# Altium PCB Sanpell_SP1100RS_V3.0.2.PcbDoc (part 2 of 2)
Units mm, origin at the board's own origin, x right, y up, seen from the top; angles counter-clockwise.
Board outline 126.12 x 87.13 mm, 4 copper layers (TopLayer, GND, PWR, BottomLayer); 152 components, 95 nets, 511 pads, 171 vias.
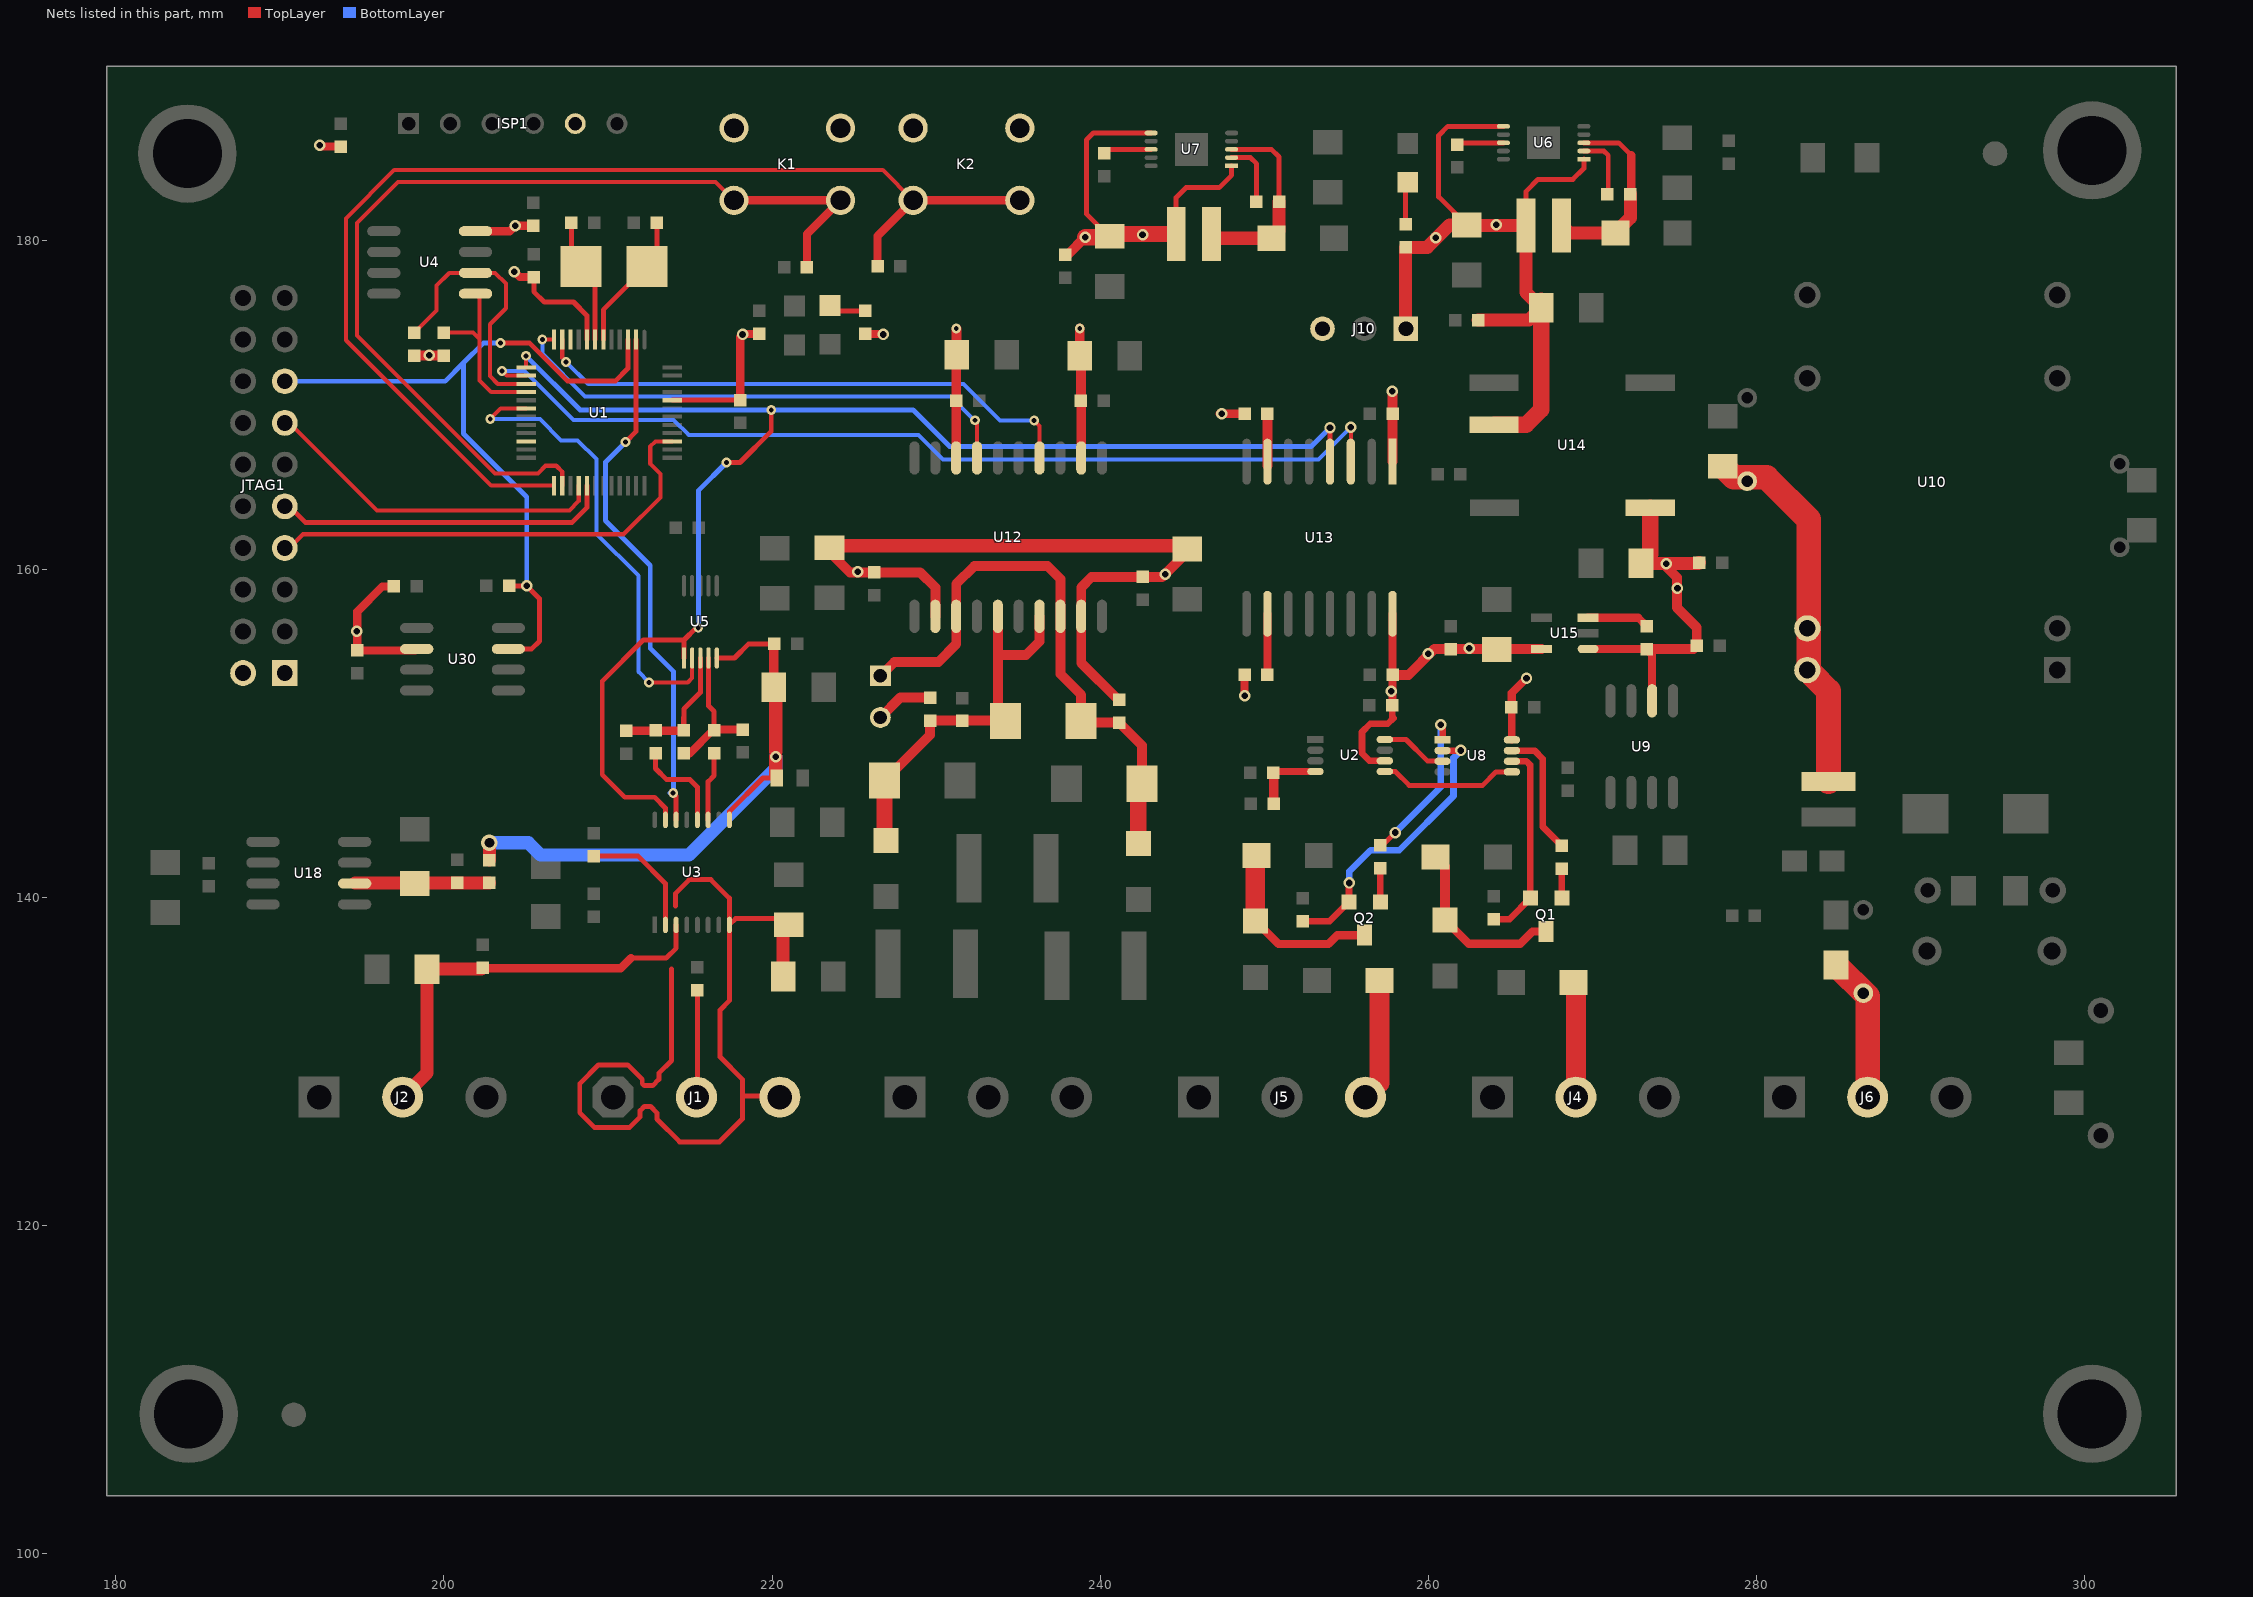
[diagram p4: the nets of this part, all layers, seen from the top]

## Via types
v1: diameter 0.7, hole 0.4, TopLayer to BottomLayer, 122 vias
v2: diameter 0.6, hole 0.3, TopLayer to BottomLayer, 40 vias
v3: diameter 1, hole 0.6, TopLayer to BottomLayer, 9 vias

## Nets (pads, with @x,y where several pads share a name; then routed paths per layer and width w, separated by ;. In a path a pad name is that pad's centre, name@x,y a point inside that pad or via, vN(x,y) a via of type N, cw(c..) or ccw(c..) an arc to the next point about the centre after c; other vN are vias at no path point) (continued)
NetD7_A: LD3.A R52.1 | length 2.2
  TopLayer w0.3: LD3.A@223.523,175.734 R52.1@225.682,175.734
NetD8_A: LD1.A R18.1 | length 2.4
  TopLayer w0.3: R18.1@258.607,181.005 LD1.A@258.607,183.448
NetFB1_1: C26.1 CA1.1 FB1.1 U18.6 | length 8.2
  TopLayer w0.8: U18.6@194.596,140.875 FB1.1@202.775,140.875
NetFB2_1: C6.1 FB2.1 U2.4 | length 4.5
  TopLayer w0.4: C6.1@250.548,147.587 250.63,147.669 U2.4@253.111,147.669
  TopLayer w0.6: C6.1@250.548,147.587 250.575,147.56 FB2.1@250.575,145.7
NetJ1_2: J1.2 R16.2 | length 6.6
  TopLayer w0.3: J1.2@215.392,127.823 215.45,127.881 R16.2@215.45,134.353
NetJ4_2: D4.2 J4.2 | length 7
  TopLayer w1.2: D4.2@268.842,134.803 268.986,134.659 J4.2@268.986,127.823
NetJ5_3: D5.2 J5.3 | length 7.5
  TopLayer w1.2: J5.3@256.159,127.823 257.017,128.681 D5.2@257.017,134.928
NetJ6_3: C04.1 F3.1 J6.2 | length 8.8
  TopLayer w1.5: F3.1@284.85,135.875 286.766,133.959 J6.2@286.766,127.823
NetL3_2: C02.1 L3.2 U10.22 U10.23 | length 23
  TopLayer w1.5: C02.1@277.925,166.277 278.6,165.602 280.598,165.602 283.175,163.025 283.175,156.39 283.175,153.935 283.188,153.913 283.41,153.55 284.375,152.585 L3.2@284.375,147.06
NetQ1_3: D1.2 F1.1 Q1.3 | length 11.1
  TopLayer w0.5: F1.1@261,138.625 262.45,137.175 265.6,137.175 266.345,137.92 Q1.3@267.165,137.92
  TopLayer w0.6: D1.2@260.44,142.447 261,141.888 F1.1@261,138.625
NetQ2_3: D2.2 F2.1 Q2.3 | length 11.5
  TopLayer w0.5: F2.1@249.45,138.554 250.854,137.15 253.9,137.15 254.445,137.695 Q2.3@256.098,137.695
  TopLayer w1.2: F2.1@249.45,138.554 249.45,142.482 D2.2@249.515,142.547
NetR3_1: C14.2 C34.1 R3.1 U5.3 | length 9.2
  TopLayer w0.3: C34.1@214.597,150.147 214.597,150.972 214.625,151 ; C34.1@214.625,150.175 214.625,151 ; U5.3@215.63,154.587 215.63,152.48 214.625,151.475 214.625,151
  TopLayer w0.5: C14.2@211.1,150.147 C34.1@214.597,150.147
NetR7_2: Q1.1 R7.2 | length 1.8
  TopLayer w0.4: Q1.1@268.13,139.952 R7.2@268.13,141.738
NetR12_1: C34.2 C35.1 R12.1 U5.4 | length 8.7
  TopLayer w0.3: U5.4@216.13,154.587 216.13,151.67 216.462,151.338 R12.1@216.462,150.181 ; R12.1@216.506,150.225 R12.1@216.575,150.294
  TopLayer w0.5: C34.2@214.625,148.778 214.984,148.778 R12.1@216.387,150.181 ; R12.1@216.506,150.225 C35.1@218.2,150.225
NetR13_2: Q2.1 R13.2 | length 2
  TopLayer w0.4: Q2.1@257.063,139.727 R13.2@257.063,141.765
NetR70_2: R70.2 U13.7 | length 3.2
  TopLayer w0.6: U13.7@250.19,166.296 R70.2@250.19,169.471
NetT1_2: R76.2 T1.2 | length 3.5
  TopLayer w0.6: T1.2@226.6,150.96 227.812,152.172 R76.2@229.625,152.172
NetU1_7: C16.1 U1.7 Y1.2 | length 7.1
  TopLayer w0.3: Y1.2@207.772,178.816 C16.1@207.772,181.102 ; Y1.2@208.344,178.435 209.217,177.562 U1.7@209.217,173.99
NetU2_5: U2.5 U8.5 | length 8.4
  TopLayer w0.3: U2.5@257.341,147.669 257.982,147.669 258.826,146.825 263.3,146.825 264.119,147.644 U8.5@265.088,147.644
NetU2_8: U2.8 U8.3 | length 4.1
  TopLayer w0.3: U2.8@257.341,149.619 258.631,149.619 259.931,148.319 U8.3@260.858,148.319
NetU3_2: R6.1 U3.2 | length 7.6
  TopLayer w0.3: R6.1@209.137,142.512 211.836,142.512 213.502,140.846 U3.2@213.502,138.321
NetU3_11: R12.2 U3.11 | length 4.3
  TopLayer w0.3: U3.11@216.102,144.721 216.102,147.052 216.462,147.412 R12.2@216.462,148.784 R12.2@216.55,148.696
NetU3_12: R3.2 U3.12 | length 5.9
  TopLayer w0.3: R3.2@212.9,148.778 212.9,147.85 213.575,147.175 215,147.175 215.452,146.723 U3.12@215.452,144.721
NetU6_2: C22.1 U6.2 | length 4
  TopLayer w0.3: U6.2@269.468,185.481 270.693,185.481 270.955,185.219 C22.1@270.955,182.85
NetU6_3: C22.2 D49.2 L1.1 U6.3 | length 11.8
  TopLayer w0.3: U6.3@269.468,185.981 271.59,185.981 272.352,185.219
  TopLayer w0.5: C22.2@272.352,182.85 272.352,185.219
  TopLayer w0.8: L1.1@268.11,180.95 268.573,180.487 D49.2@271.386,180.487 272.307,181.408 C22.2@272.307,182.85
NetU6_8: R8.1 U6.8 | length 2.9
  TopLayer w0.3: R8.1@261.76,185.875 261.866,185.981 U6.8@264.568,185.981
NetU7_2: C10.1 U7.2 | length 4
  TopLayer w0.3: U7.2@248.002,185.079 249.153,185.079 249.526,184.706 C10.1@249.526,182.4
NetU7_3: C10.2 D9.2 L2.1 U7.3 | length 11.6
  TopLayer w0.3: U7.3@248.002,185.579 250.431,185.579 250.897,185.113 C10.2@250.897,182.4
  TopLayer w0.8: L2.1@247.041,180.164 D9.2@250.44,180.164 250.897,180.621 C10.2@250.897,182.4
NetU7_8: R11.1 U7.8 | length 2.9
  TopLayer w0.3: R11.1@240.25,185.35 240.479,185.579 U7.8@243.102,185.579
NetU8_1: R13.1 U8.1 | length 9.9
  TopLayer w0.3: R13.1@257.063,143.162 257.187,143.162 v1(257.975,143.95)
  TopLayer w0.4: v1(260.75,150.525) 260.858,150.417 U8.1@260.858,149.594
  BottomLayer w0.4: v1(257.975,143.95) 260.75,146.725 v1(260.75,150.525)
NetU8_2: Q2.2 R4.1 U8.2 | length 17.5
  TopLayer w0.4: R4.1@252.325,138.55 253.981,138.55 Q2.2@255.158,139.727 255.158,140.858 v1(255.175,140.875) ; U8.2@260.858,148.944 261.969,148.944 v1(261.975,148.95)
  BottomLayer w0.4: v1(255.175,140.875) 255.175,141.575 256.475,142.875 258.225,142.875 261.525,146.175 261.525,148.5 v1(261.975,148.95)
NetU8_6: Q1.2 R5.1 U8.6 | length 12.1
  TopLayer w0.4: R5.1@263.975,138.675 264.948,138.675 Q1.2@266.225,139.952 266.192,139.985 266.192,148.07 265.968,148.294 U8.6@265.088,148.294
NetU8_7: R7.1 U8.7 | length 7.9
  TopLayer w0.4: U8.7@265.088,148.944 266.461,148.944 266.954,148.451 266.954,144.311 R7.1@268.13,143.135
NetU12_13: F10.1 R41.2 T1.1 U12.13 U12.18 ZD14.1 ZD15.1 | length 36.2
  TopLayer w0.6: T1.1@226.6,153.5 227.45,154.35 230.15,154.35 231.22,155.42 U12.13@231.22,157.123 231.22,159.095 232.325,160.2 236.779,160.2 237.57,159.409 U12.18@237.57,157.123 237.57,153.605 238.825,152.35 ZD14.1@238.825,150.75 238.922,150.653 R41.2@241.15,150.653 242.55,149.253 ZD15.1@242.55,146.925 ; F10.1@242.316,142.94 F10.1@242.316,143.29
  TopLayer w1: F10.1@242.316,143.29 242.316,146.691 ZD15.1@242.55,146.925
NetU12_15: F11.1 R42.1 R76.1 U12.15 U12.17 ZD14.2 ZD16.2 | length 24.1
  TopLayer w0.6: ZD16.2@226.85,147.125 229.625,149.9 R76.1@229.625,150.775 ZD14.2@234.2,150.775 ; U12.15@233.76,157.123 233.76,154.95 ; ZD14.2@234.225,150.75 ZD14.2@234.2,150.775 ; U12.17@236.3,157.123 236.3,155.6 235.475,154.775 233.935,154.775 233.76,154.95 ; 233.76,154.95 233.76,151.215 ZD14.2@234.2,150.775
  TopLayer w1: ZD16.2@226.85,147.125 226.85,143.574 F11.1@226.949,143.475
NetU13_10: R71.1 U13.10 | length 3.7
  TopLayer w0.5: R71.1@250.19,153.556 U13.10@250.19,157.279
NetU15_3: R72.2 U15.3 | length 3.8
  TopLayer w0.5: U15.3@269.73,157.038 272.784,157.038 R72.2@273.3,156.522
NetY1_1: C15.1 U1.6 Y1.1 | length 9.3
  TopLayer w0.3: U1.6@209.717,173.99 209.717,175.808 212.344,178.435 Y1.1@212.369,178.435 Y1.1@211.328,177.394 ; Y1.1@212.979,178.816 C15.1@212.979,181.102
PT1000: C25.1 C30.1 J2.2 U3.3 | length 25.5
  TopLayer w0.3: 211.4,136.3 213.55,136.3 214.152,136.902 U3.3@214.152,138.321
  TopLayer w0.5: C30.1@202.35,135.675 210.775,135.675 211.4,136.3
  TopLayer w0.8: J2.2@197.485,127.823 198.975,129.313 C25.1@198.975,135.625 C30.1@202.3,135.625
R\E\S\E\T\: JTAG1.15 R68.2 U1.3 U30.7 | length 46.7
  TopLayer w0.3: v2(203.45,173.775) 205.225,173.775 207.525,171.475 210.464,171.475 211.217,172.228 U1.3@211.217,173.99 ; U30.7@203.934,155.14 205.357,155.14 205.825,155.608 205.825,158.2 v1(205.05,158.975) R68.2@203.972,158.975
  BottomLayer w0.3: JTAG1.15@190.581,171.45 200.075,171.45 201.2,172.575 ; v2(203.45,173.775) 202.4,173.775 201.2,172.575 ; v1(205.05,158.975) 205.05,164.4 201.2,168.25 201.2,172.575
REF2.5V: C8.1 C11.1 C17.1 FB1.2 U3.9 U5.5 | length 37.6
  TopLayer w0.3: U5.5@216.63,154.587 217.713,154.587 218.575,155.45 C11.1@220.125,155.45 ; U3.9@217.402,144.721 217.402,145.227 219.45,147.275 C8.1@220.275,147.275 ; C17.1@219.929,152.396 C17.1@219.975,152.35
  TopLayer w0.6: C11.1@220.1,155.275 C17.1@220.1,152.8 C17.1@220.225,152.675
  TopLayer w0.8: FB1.2@202.775,142.272 v3(202.775,143.325) ; C8.1@220.225,147.325 v1(220.225,148.575) ; v1@220.225,148.85 C17.1@220.225,152.675
  BottomLayer w0.8: v3(202.775,143.325) 205.146,143.325 205.896,142.575 214.925,142.575 220.225,147.875 v1(220.225,148.575)
RX485: U1.11 U12.4 | length 33.9
  TopLayer w0.25: U1.11@207.217,173.99 207.217,172.858 v2(207.45,172.625) ; v2(235.975,169.05) 236.3,168.725 U12.4@236.3,166.775
  BottomLayer w0.25: v2(207.45,172.625) 208.8,171.275 231.675,171.275 233.9,169.05 v2(235.975,169.05)
SCK0: U1.22
SCK1: U1.13 U3.15 U5.1 U13.4 | length 89.6
  TopLayer w0.25: v2(205,173) 205.017,172.983 U1.13@205.017,172.29
  TopLayer w0.3: U3.15@213.502,144.721 213.502,145.448 212.85,146.1 211.025,146.1 209.65,147.475 209.65,153.175 212.155,155.68 214.63,155.68 ; U5.1@214.63,154.587 214.63,155.68 ; v2@215.375,156.425 214.63,155.68 ; v2(217.225,166.5) 218.05,166.5 219.95,168.4 v2(219.95,169.7) ; U13.4@254,166.55 v1(254,168.625)
  BottomLayer w0.3: v2(205,173) 208.3,169.7 v2(219.95,169.7) 228.6,169.7 230.825,167.475 252.85,167.475 v1(254,168.625) ; v2@215.525,156.275 215.525,164.8 v2(217.225,166.5)
  other v2: 215.5,156.425
SCL: R14.1 U1.15 U4.6 | length 16.7
  TopLayer w0.25: R14.1@198.206,174.416 199.55,175.76 199.55,177.275 200.329,178.054 U4.6@201.93,178.054 203.121,178.054 203.775,177.4 203.775,175.9 202.8,174.925 202.8,171.775 203.285,171.29 U1.15@205.017,171.29
SDA: R15.1 U1.16 U4.5 | length 10.9
  TopLayer w0.25: R15.1@199.984,174.416 201.779,174.416 202.175,174.019 ; U4.5@201.93,176.784 202.175,176.539 202.175,174.019 ; U1.16@205.017,170.79 202.885,170.79 202.175,171.5 202.175,174.019
SSEL0: U1.10
SSEL1: U1.18 U5.2 | length 28.9
  TopLayer w0.25: v2(202.825,169.15) 203.465,169.79 U1.18@205.017,169.79 ; v2(212.5,153.1) 212.512,153.088 214.862,153.088 215.13,153.355 U5.2@215.13,154.587
  BottomLayer w0.25: v2(202.825,169.15) 205.85,169.15 207.15,167.85 208.15,167.85 209.3,166.7 209.3,162.15 211.85,159.6 211.85,153.75 v2(212.5,153.1)
SSEL1_A: U1.2 U3.14 | length 32.1
  TopLayer w0.3: v2(211.075,167.75) 211.717,168.392 U1.2@211.717,173.99 ; v2(213.975,146.35) 214.152,146.173 U3.14@214.152,144.721
  BottomLayer w0.3: v2(211.075,167.75) 209.85,166.525 209.85,162.95 212.575,160.225 212.575,155.175 214,153.75 214,146.575 213.775,146.35 v2(213.975,146.35)
SSEL1_B: U1.14 U13.3 | length 58.5
  TopLayer w0.25: v2(203.55,172.075) 203.835,171.79 U1.14@205.017,171.79 ; U13.3@255.27,166.55 255.27,168.645 v1(255.275,168.65)
  BottomLayer w0.25: v2(203.55,172.075) 204.925,172.075 207.9,169.1 214,169.1 214.925,168.175 228.925,168.175 230.425,166.675 253.3,166.675 v1(255.275,168.65)
SW_S1: K1.2 K1.4 R73.2 U1.26 | length 60
  TopLayer w0.25: U1.26@207.217,165.09 207.217,165.933 206.85,166.3 206.2,166.3 205.725,165.825 203.125,165.825 194.7,174.25 194.7,181.1 197.2,183.6 216.551,183.6 K1.2@217.676,182.475
  TopLayer w0.5: K1.2@217.676,182.475 K1.4@224.176,182.475 222.125,180.424 R73.2@222.125,178.4
SW_S2: K2.2 K2.4 R74.2 U1.25 | length 71.8
  TopLayer w0.25: U1.25@206.717,165.09 202.885,165.09 194.025,173.95 194.025,181.375 196.975,184.325 226.748,184.325 K2.2@228.598,182.475
  TopLayer w0.5: R74.2@226.428,178.45 226.428,180.305 K2.2@228.598,182.475 K2.4@235.098,182.475
SWCLK: JTAG1.9 U1.29 | length 20.3
  TopLayer w0.3: JTAG1.9@190.581,163.83 191.561,162.85 207.825,162.85 208.717,163.742 U1.29@208.717,165.09
SWDIO: JTAG1.7 U1.39 | length 28.7
  TopLayer w0.25: JTAG1.7@190.581,161.29 191.416,162.125 210.95,162.125 213.2,164.375 213.2,165.8 212.575,166.425 212.575,167.475 212.89,167.79 U1.39@213.917,167.79
SWO: JTAG1.13 U1.28 | length 21
  TopLayer w0.25: JTAG1.13@190.581,168.91 195.916,163.575 207.65,163.575 208.217,164.142 U1.28@208.217,165.09
TX485: U1.12 U12.7 | length 32.1
  TopLayer w0.25: v2(206,174) 206.01,173.99 U1.12@206.717,173.99 ; v2(232.375,169.075) 232.5,168.95 232.5,166.785 U12.7@232.49,166.775
  BottomLayer w0.25: v2(206,174) 206,173.125 208.6,170.525 230.875,170.525 232.375,169.025 v2(232.375,169.075)
V300_L: C5.1 C55.1 C57.1 CA25.1 R71.2 U2.6 U13.16 U15.5 | length 22.5
  TopLayer w0.4: U2.6@257.341,148.319 256.406,148.319 255.95,148.775 255.95,150.075 256.45,150.575 257.525,150.575 257.875,150.925 257.8,151 C5.1@257.8,151.7
  TopLayer w0.5: v1(248.793,152.286) R71.2@248.793,153.556 ; C5.1@257.81,151.725 C57.1@257.81,153.556 U13.16@257.81,157.279
  TopLayer w0.6: C57.1@257.81,153.556 258.781,153.556 260.35,155.125 C55.1@261.35,155.125 261.363,155.138 U15.5@266.88,155.138
  other v1: 257.725,152.55 260,154.85 262.475,155.175
V330_D: C3.1 C4.1 C13.1 C27.1 C28.1 C43.1 C44.1 C56.1 C58.1 CA13.1 CA14.1 ISP1.5 J10.3 JTAG1.1 JTAG1.2 K1.1 K1.3 K2.1 K2.3 L2.2 R1.2 R14.2 R15.2 R17.2 R52.2 R69.1 R70.1 U1.8 U1.44 U4.8 U7.1 U7.6 U12.2 U12.8 U13.1 U30.2 | length 80.1
  TopLayer w0.3: C4.1@205.486,177.8 205.486,176.911 206.121,176.276 207.899,176.276 208.717,175.458 U1.8@208.717,173.99 ; U1.44@213.917,170.307 C3.1@218.2,170.307 ; C13.1@240.575,180.225 240.45,180.35 239.15,181.65 239.15,186.15 239.579,186.579 U7.6@243.102,186.579 ; L2.2@244.624,180.421 244.624,182.649 245.225,183.25 247.25,183.25 248.002,184.002 U7.1@248.002,184.579
  TopLayer w0.5: v1@192.497,185.753 R1.2@193.725,185.753 ; R69.1@196.947,158.944 196.244,158.944 194.725,157.425 C27.1@194.725,155.05 198.257,155.05 U30.2@198.346,155.14 ; U4.8@201.93,180.594 204.019,180.594 v1(204.35,180.925) C28.1@205.425,180.925 ; v1(204.3,178.125) 204.625,177.8 C4.1@205.486,177.8 ; C3.1@218.059,170.307 218.059,174.159 v1(218.2,174.3) 218.237,174.337 R17.2@219.234,174.337 ; R52.2@225.682,174.337 226.738,174.337 v1(226.775,174.3) ; v1@247.269,169.471 v1(247.396,169.471) R70.1@248.793,169.471
  TopLayer w0.6: R14.2@198.206,173.019 R15.2@199.984,173.019 ; U12.8@231.22,166.775 CA14.1@231.22,173.29 ; CA14.1@231.25,173.075 v2@231.25,174.65 ; C58.1@237.875,179.15 238,179.15 v1(239.075,180.225) ; v2(238.75,174.675) CA13.1@238.75,173 238.825,172.925 C43.1@238.825,170.25 ; U12.2@238.84,166.775 C43.1@238.84,170.25 ; v1(257.8,170.85) 257.8,170.7 257.81,170.69 C56.1@257.81,169.471 U13.1@257.81,166.55
  TopLayer w1: v1(239.075,180.225) C13.1@240.575,180.225 ; C13.1@240.45,180.35 240.521,180.421 L2.2@244.624,180.421
  other v1: 194.7,156.225 199.1,173.025 242.575,180.375 192.425,185.825
  other v2: 231.225,174.675
V500_A: C23.1 C24.1 C51.1 J10.1 L1.2 R18.2 U6.1 U6.6 U14.2 | length 49
  TopLayer w0.3: C23.1@262.36,180.95 C23.1@262.335,180.975 260.625,182.685 260.625,186.425 261.181,186.981 U6.6@264.568,186.981 ; L1.2@265.95,180.95 265.95,183.025 266.675,183.75 268.8,183.75 269.468,184.418 U6.1@269.468,184.981
  TopLayer w0.8: J10.1@258.607,175.05 R18.2@258.607,179.608 259.933,179.608 261.3,180.975 C23.1@262.335,180.975 ; C23.1@262.36,180.95 L1.2@265.95,180.95 265.95,176.85 C24.1@266.875,175.925 266.125,175.175 C51.1@263.025,175.175
  TopLayer w1: U14.2@264,168.81 265.96,168.81 266.875,169.725 C24.1@266.875,175.925 C24.1@266.875,176.35
  other v1: 260.45,180.2 264.125,180.975
V500_LA: C2.1 C52.1 C53.1 CA23.1 R72.1 U8.8 U9.2 U14.5 U15.1 | length 27.2
  TopLayer w0.457: U8.8@265.088,149.594 C2.1@265.088,151.575
  TopLayer w0.5: C2.1@265.049,151.593 265.075,151.619 265.075,152.45 v1(265.975,153.35) v1@266.025,153.4 ; U15.1@269.73,155.138 269.742,155.125 R72.1@273.3,155.125 273.63,154.795 U9.2@273.63,151.975
  TopLayer w0.6: R72.1@273.3,155.125 276.15,155.125 C53.1@276.35,155.325 276.35,156.45 275.15,157.65 275.15,159.5 v1@274.3,160.35
  TopLayer w0.8: CA23.1@272.95,160.35 274.3,160.35 276.45,160.35 C52.1@276.5,160.4
  TopLayer w1: CA23.1@272.95,160.35 273.51,160.91 U14.5@273.51,163.73
  other v1: 275.175,158.825 274.5,160.325
VCC_COM: C45.1 C46.2 CA15.1 CA16.1 R41.1 U12.12 U12.19 | length 46.4
  TopLayer w0.6: CA15.1@223.5,161.05 224.753,159.797 C45.1@226.225,159.797 229.028,159.797 229.95,158.875 U12.12@229.95,157.123 ; R41.1@241.15,152.05 241.075,152.05 238.84,154.285 U12.19@238.84,157.123 238.84,158.89 239.475,159.525 C46.2@242.6,159.525 243.775,159.525 CA16.1@245.3,161.05
  TopLayer w0.8: CA15.1@223.5,161.05 223.875,161.425 244.925,161.425 CA16.1@245.3,161.05
  other v1: 243.95,159.7 225.225,159.85
VCM: C29.1 C31.1 J1.3 U3.8 | length 55.9
  TopLayer w0.3: 213.868,135.65 213.868,130.048 213.106,129.286 213.106,128.905 212.725,128.524 212.217,128.524 212.09,128.651 212.09,128.905 211.201,129.794 209.423,129.794 208.28,128.651 208.28,126.873 209.169,125.984 211.328,125.984 211.963,126.619 211.963,127 212.217,127.254 212.598,127.254 212.979,126.873 212.979,126.492 214.371,125.1 216.794,125.1 218.186,126.492 218.186,127.889 ; 214.125,139.475 214.125,140.25 214.95,141.075 216.275,141.075 217.402,139.948 U3.8@217.402,138.321 ; J1.3@220.406,127.889 218.186,127.889 ; C29.1@220.775,138.7 217.781,138.7 U3.8@217.402,138.321 ; U3.8@217.402,138.321 217.402,133.702 216.825,133.125 216.825,130.275 218.186,128.914 218.186,127.889
  TopLayer w0.8: C31.1@220.677,135.175 220.677,137.979 C29.1@221.025,138.327
pads on no net: J2.3 JTAG1.3 JTAG1.5 JTAG1.11 JTAG1.17 JTAG1.19 U1.1 U1.19 U1.20 U1.21 U1.23 U1.24 U1.27 U1.31 U1.36 U1.40 U1.42 U1.43 U1.45 U1.48 U3.6 U3.7 U6.5 U6.7 U6.9 U7.5 U7.7 U7.9 U9.1 U9.3 U9.5 U9.7 U9.8 U10.9 U10.11 U13.6 U13.11 U14.8 U15.4 U18.1 U18.3 U18.5 U18.7 U18.8 U30.4 U30.5 U30.6 U30.8

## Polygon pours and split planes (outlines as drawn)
IAGND on BottomLayer "Top Layer-No Net" (hatched 90Degree grid 0.3 track 0.3, remove dead copper, pour order 24): 247.175,161.775 278.675,161.775 278.9,161.55 278.9,138.15 277.55,136.8 247.175,136.8
GND on BottomLayer "Top Layer-No Net" (hatched 90Degree grid 0.3 track 0.3, remove dead copper, pour order 20): 192.467,180.525 225.792,180.525 230.317,175.629 230.674,175.243 251.828,175.243 251.828,164.219 251.85,164.195 212.796,164.195 201.316,151.773 201.272,151.725 192.4,151.725
EARTH on BottomLayer "TopLayer-EARTH" (hatched 90Degree grid 0.3 track 0.3, remove dead copper, pour order 21): 179.705,122.479 179.705,103.505 304.546,103.505 304.546,123.2 179.705,123.2
AGND on BottomLayer "Top Layer-No Net" (hatched 90Degree grid 0.3 track 0.3, remove dead copper, pour order 17): 182.975,147.85 182.975,147.075 182.975,132.6 183.05,132.525 210.525,132.525 210.525,145.625 208.3,147.85
IAGND on TopLayer "Top Layer-No Net" (hatched 90Degree grid 0.3 track 0.3, remove dead copper, pour order 23): 246.975,161.825 278.475,161.825 278.7,161.6 278.7,138.2 277.35,136.85 246.975,136.85
GND on TopLayer "Top Layer-No Net" (hatched 90Degree grid 0.3 track 0.3, remove dead copper, pour order 19): 223.435,175.275 251.781,175.275 251.83,175.214 251.83,164.013 251.85,163.988 224.789,163.988 223.375,165.725
GND on TopLayer "Top Layer-No Net" (hatched 90Degree grid 0.3 track 0.3, remove dead copper, pour order 22): 225.575,180.125 225.575,163.925 225.65,163.85 215.85,163.85 204.8,152.8 202.625,150.625 192.425,150.625 192.425,179.575 193.05,180.2
V500_A on TopLayer "Top Layer-No Net" (hatched 90Degree grid 0.3 track 0.3, remove dead copper, pour order 18): 266.725,183.35 266.725,179.25 266.675,179.2 260.1,179.2 260.05,179.25 260.05,183.175 260.225,183.35
V330_D on TopLayer "Top Layer-No Net" (hatched 90Degree grid 0.3 track 0.3, remove dead copper, pour order 16): 237.575,182.775 245.275,182.775 245.3,182.8 245.3,178.725 245.275,178.7 237.65,178.7 237.575,178.775
V500_LA on TopLayer "Top Layer-No Net" (hatched 90Degree grid 0.3 track 0.3, remove dead copper, pour order 15): 271.875,164.3 276.375,164.3 276.4,164.276 276.4,157.974 276.425,157.95 271.9,157.95 271.85,157.998
NetL3_2 on TopLayer "Top Layer-No Net" (hatched 90Degree grid 0.3 track 0.3, remove dead copper, pour order 25): 281.475,160.65 286.2,160.65 286.275,160.575 287.15,160.575 287.175,160.55 287.175,146.325 287.25,146.25 281.9,146.25 281.5,146.65
24VGND_IN on TopLayer "Top Layer-No Net" (hatched 90Degree grid 0.3 track 0.3, remove dead copper, pour order 26): 300.8,160.575 300.8,151.025 300.7,150.925 296.5,150.925 296.4,150.825 296.4,161.25 297.7,162.55 297.8,162.65 300.75,162.65
GND on TopLayer "Top Layer-No Net" (hatched 90Degree grid 0.3 track 0.3, remove dead copper, pour order 27): 281.725,173.275 290.561,173.275 293.402,170.33 294.001,169.709 296.921,169.709 296.921,166.008 297.025,165.9 290.405,165.9 288.372,168.007 287.146,169.277 281.725,169.277
+24V on TopLayer "Top Layer-No Net" (hatched 90Degree grid 0.3 track 0.3, remove dead copper, pour order 28): 281.5,174.774 287.2,174.774 287.225,174.75 287.225,182 281.675,182 281.475,181.809
IAGND on GND (split plane): 278.948,137.229 277.022,135.303 276.982,135.251 276.956,135.19 276.948,135.125 276.948,124.202 241.902,124.202 241.902,130.821 246.628,135.547 246.668,135.599 246.694,135.66 246.702,135.725 246.702,160.323 258.225,160.323 258.29,160.331 258.351,160.357 258.403,160.397 259.979,161.973 278.948,161.973
GND_COM on GND (split plane): 246.198,135.829 241.472,131.103 241.432,131.051 241.406,130.99 241.398,130.925 241.398,124.202 223.752,124.202 223.752,160.323 246.198,160.323
24VGND_IN on GND (split plane): 305.059,124.202 277.452,124.202 277.452,135.021 279.378,136.947 279.401,136.976 279.418,136.999 279.426,137.017 279.444,137.06 279.452,137.125 279.452,161.973 305.059,161.973
GND on GND (split plane): 305.059,162.477 261.552,162.477 261.552,167.2 261.544,167.265 261.518,167.326 261.478,167.378 261.426,167.418 261.365,167.444 261.3,167.452 258.625,167.452 258.56,167.444 258.499,167.418 258.447,167.378 258.407,167.326 258.381,167.265 258.373,167.2 258.373,165.354 256.946,163.927 215.4,163.927 215.335,163.919 215.274,163.893 215.222,163.853 213.722,162.353 199.896,148.527 179.96,148.527 179.96,190.139 305.059,190.139
AGND on GND (split plane): 261.048,162.477 259.875,162.477 259.81,162.469 259.749,162.443 259.697,162.403 258.121,160.827 223.5,160.827 223.435,160.819 223.374,160.793 223.322,160.753 223.282,160.701 223.256,160.64 223.248,160.575 223.248,131.7 218.6,131.7 218.575,131.725 218.575,142.2 218.55,142.175 212.725,142.175 212.7,131.725 206.2,131.725 206.175,131.7 206.175,124.202 179.96,124.202 179.96,148.023 200,148.023 200.065,148.031 200.126,148.057 200.178,148.097 214.078,161.997 215.504,163.423 257.05,163.423 257.115,163.431 257.176,163.457 257.228,163.497 258.803,165.072 258.843,165.124 258.869,165.185 258.877,165.25 258.877,166.948 261.048,166.948
+24V on PWR (split plane): 305.059,162.477 276.177,162.477 276.177,190.139 305.059,190.139
V500_LA on PWR (split plane): 278.973,149.302 265.002,149.302 265.002,161.973 278.973,161.973
V500_A on PWR (split plane): 275.673,162.477 265.002,162.477 265.002,176.4 264.994,176.465 264.968,176.526 264.928,176.578 264.876,176.618 264.815,176.644 264.75,176.652 257.627,176.652 257.627,190.139 275.673,190.139
IREF2.5V on PWR (split plane): 278.973,137.304 278.296,136.627 246.752,136.627 246.752,145.798 261.75,145.798 261.815,145.806 261.876,145.832 261.928,145.872 264.854,148.798 278.973,148.798
V300_L on PWR (split plane): 264.498,149.154 261.646,146.302 246.752,146.302 246.752,160.648 264.498,160.648
+24V_IN on PWR (split plane): 305.059,124.277 241.902,124.277 241.902,130.771 246.678,135.547 246.718,135.599 246.744,135.66 246.752,135.725 246.752,136.123 278.4,136.123 278.465,136.131 278.526,136.157 278.578,136.197 279.403,137.022 279.443,137.074 279.469,137.135 279.477,137.2 279.477,161.973 305.059,161.973
V330_D on PWR (split plane): 257.123,176.652 254.9,176.652 254.835,176.644 254.774,176.618 254.722,176.578 254.682,176.526 254.656,176.465 254.648,176.4 254.648,172.275 254.656,172.21 254.682,172.149 254.722,172.097 254.774,172.057 254.835,172.031 254.9,172.023 259.073,172.023 259.073,169.129 257.471,167.527 219.325,167.527 219.26,167.519 219.217,167.501 219.199,167.493 219.176,167.476 219.147,167.453 200.121,148.427 179.96,148.427 179.96,190.139 257.123,190.139
AVCC on PWR (split plane): 264.498,162.225 264.498,161.152 224.9,161.152 224.835,161.144 224.774,161.118 224.722,161.078 223.897,160.253 223.857,160.201 223.831,160.14 223.823,160.075 223.823,124.277 223.45,124.277 223.45,131.625 218.6,131.625 218.575,131.65 218.575,142.125 218.55,142.1 212.725,142.1 212.7,131.65 206.2,131.65 206.175,131.625 206.175,124.277 179.96,124.277 179.96,147.923 200.225,147.923 200.29,147.931 200.351,147.957 200.403,147.997 219.429,167.023 257.575,167.023 257.64,167.031 257.701,167.057 257.753,167.097 259.503,168.847 259.543,168.899 259.569,168.96 259.577,169.025 259.577,172.275 259.569,172.34 259.543,172.401 259.503,172.453 259.451,172.493 259.39,172.519 259.325,172.527 255.152,172.527 255.152,176.148 264.498,176.148
VCC_COM on PWR (split plane): 246.248,135.829 241.472,131.053 241.432,131.001 241.406,130.94 241.398,130.875 241.398,124.277 224.404,124.277 224.327,124.354 224.327,159.971 225.004,160.648 246.248,160.648

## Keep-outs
KeepOutLayer:
  lines w0.3: 179.442,103.522 192.442,103.522 292.442,103.522 305.442,103.522 305.442,190.522 292.442,190.522 192.442,190.522 179.442,190.522 179.442,103.522

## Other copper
BottomLayer:
  pour cut-out: 212.7,142.075 218.525,142.075 218.55,142.1 218.55,131.625 218.575,131.6 223.425,131.6 223.425,123.7 223.45,123.675 206.2,123.675 206.15,123.725 206.15,131.6 206.175,131.625 212.675,131.625
GND (plane layer: these items are gaps in the copper):
  pour cut-out: 212.725,142.175 218.55,142.175 218.575,142.2 218.575,131.725 218.6,131.7 223.45,131.7 223.45,123.8 223.475,123.775 206.225,123.775 206.175,123.825 206.175,131.7 206.2,131.725 212.7,131.725
  pour cut-out: 178.325,124.075 307.175,124.075 307.375,124.275 307.375,101.475 307.1,101.2 179.075,101.2 178.325,101.95
  lines w0.5: 179.45,148.275 200,148.275 213.9,162.175 215.4,163.675 257.05,163.675 258.625,165.25 258.625,167.2 261.3,167.2 ; 179.525,123.95 305.45,123.95 ; 223.5,124 223.5,160.575 246.45,160.575 ; 241.65,123.925 241.65,130.925 246.45,135.725 246.45,160.575 ; 260.575,167.2 261.3,167.2 ; 261.3,162.275 261.3,167.2 ; 277.2,123.95 277.2,135.125 279.2,137.125 279.2,162.225 ; 305.442,162.225 279.2,162.225 ; 246.45,160.575 258.225,160.575 259.875,162.225 279.2,162.225
PWR (plane layer: these items are gaps in the copper):
  pour cut-out: 212.725,142.1 218.55,142.1 218.575,142.125 218.575,131.65 218.6,131.625 223.45,131.625 223.45,123.725 223.475,123.7 206.225,123.7 206.175,123.75 206.175,131.625 206.2,131.65 212.7,131.65
  pour cut-out: 178.2,124.025 307.05,124.025 307.25,124.225 307.25,101.425 306.975,101.15 178.95,101.15 178.2,101.9
  lines w0.5: 179.442,148.175 200.225,148.175 219.325,167.275 257.575,167.275 259.325,169.025 259.325,172.275 254.9,172.275 254.9,176.4 264.75,176.4 264.75,162.225 ; 179.492,124.025 305.442,124.025 ; 224.3,124.025 224.075,124.25 224.075,160.075 224.9,160.9 246.5,160.9 ; 241.65,123.975 241.65,130.875 246.5,135.725 246.5,160.9 ; 246.5,146.05 261.75,146.05 264.75,149.05 ; 246.525,136.375 278.4,136.375 279.225,137.2 279.225,162.225 ; 257.375,176.45 257.375,190.624 ; 264.75,160.9 246.5,160.9 ; 275.925,162.25 275.925,190.775 ; 279.2,149.05 264.75,149.05 ; 305.4,162.225 279.225,162.225 ; 264.75,149.05 264.75,162.225 ; 264.75,162.225 279.225,162.225

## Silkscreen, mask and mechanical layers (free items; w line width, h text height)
TopOverlay:
  lines w0.3: 225.171,110.874 226.187,113.033 227.838,113.033 ; 226.822,110.874 227.838,113.033 ; 227.838,113.75 227.838,113.033 ; 228.473,110.874 229.489,113.033 227.838,113.033 ; 243.078,110.874 244.094,113.033 245.745,113.033 ; 244.729,110.874 245.745,113.033 ; 245.688,113.158 245.688,113.875 ; 246.38,110.874 247.396,113.033 245.745,113.033 ; 271.145,110.874 272.161,113.033 273.812,113.033 ; 272.796,110.874 273.812,113.033 ; 273.763,113.083 273.763,113.8 ; 274.447,110.874 275.463,113.033 273.812,113.033 ; 278.511,110.874 279.527,113.033 281.178,113.033 ; 280.162,110.874 281.178,113.033 ; 281.113,113.158 281.113,113.875 ; 281.813,110.874 282.829,113.033 281.178,113.033
  text "5V" at 258.075,172 h0.8
  text "3V3" at 252.525,171.9 h0.8
  text "+" at 287.45,144.35 h1.52
  text "+" at 228.092,129.54 h1.52 r180
  text "T\P-" at 191.211,121.895 h1.52 r270
  text "T\P+" at 196.774,121.895 h1.52 r270
  text "NC" at 202.057,121.895 h1.52 r270
  text "GUARD" at 208.915,121.895 h1.52 r270
  text "INP" at 214.681,121.895 h1.52 r270
  text "VCM" at 219.786,121.895 h1.52 r270
  text "EARTH" at 227.025,121.895 h1.52 r270
  text "485D-" at 232.105,121.895 h1.52 r270
  text "485D+" at 237.312,121.895 h1.52 r270
  text "EARTH" at 244.831,121.895 h1.52 r270
  text "A(MA)-" at 249.987,121.895 h1.52 r270
  text "A(MA)+" at 255.27,121.895 h1.52 r270
  text "B(MA)-" at 262.915,121.895 h1.52 r270
  text "B(MA)+" at 268.3,121.895 h1.52 r270
  text "EARTH" at 273.075,121.895 h1.52 r270
  text "EARTH" at 280.492,121.895 h1.52 r270
  text "+24V" at 285.85,121.85 h1.52 r270
  text "GND" at 291.1,121.85 h1.52 r270
  text "Sanpell_SP1100RS_V3.0.2 2017.10" at 218.6,106.925 h1.52
Mechanical1:
  lines w0.3: 181.014,185.323 309.298,185.323 ; 181.086,108.522 309.672,108.522 ; 184.442,108.522 184.442,195.483 ; 300.442,108.522 300.442,195.692

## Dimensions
179.442,103.522 to 305.442,103.522 on Mechanical1
192.442,103.522 to 179.442,190.522 on Mechanical1
300.442,108.522 to 184.442,108.522 on Mechanical1
184.442,108.522 to 184.37,185.323 on Mechanical1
